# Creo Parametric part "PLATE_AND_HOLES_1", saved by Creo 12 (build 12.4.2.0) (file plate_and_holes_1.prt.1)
Units: Custom; MM, KILOGRAM, SECS

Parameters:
  PTC_WM_ITERATION = "0"
  PTC_WM_VERSION = "-.0"
  PTC_WM_LIFECYCLE_STATE = "In Work"
  PTC_WM_LIFECYCLE = "MO_CADDocument"
  PTC_WM_CREATED_BY = "Maximilian Roepper (Z0017RMS: MO)"
  PTC_WM_CREATED_ON = "18-Sep-26 11:36:42 AM"
  PTC_WM_MODIFIED_BY = "Maximilian Roepper (Z0017RMS: MO)"
  PTC_WM_MODIFIED_ON = "18-Sep-26 11:36:46 AM"
  PDMLINKNUMBER = "PDM000071454987"
  PTC_WM_NAME = "plate_and_holes_1.prt"
  PTC_WM_NUMBER = "PDM000071454987"

Other parameters: WEIGHT, WEIGHT_FACTOR, WEIGHT_ADD, _MASS_TEMP, _DIFF_TEMP, MC_ERRORS, SUPPLIER

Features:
  1. coordinate system
  2. datum plane "PRT_YZ"
  3. datum plane "PRT_XY"
  4. datum plane "PRT_XZ"
  5. coordinate system
  6. datum axis
  7. datum axis
  8. datum axis
  9. coordinate system
  10. imported feature
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
Other named items: PRT, SIEMENS_MO, DRW_VIEW_ORG, PRT_X, PRT_Y, PRT_Z, CS0, ROUGH_GROB

Layers: 00_STD_CSYS-KSYS, 01_STD_PLANES-EBENEN, 02_STD_AXES-ACHSEN, 03_STD_CSYS-KSYS, 24_IMPORT_FEAT-IMPORT_KE

Surfaces: 48 cylinder, 10 plane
